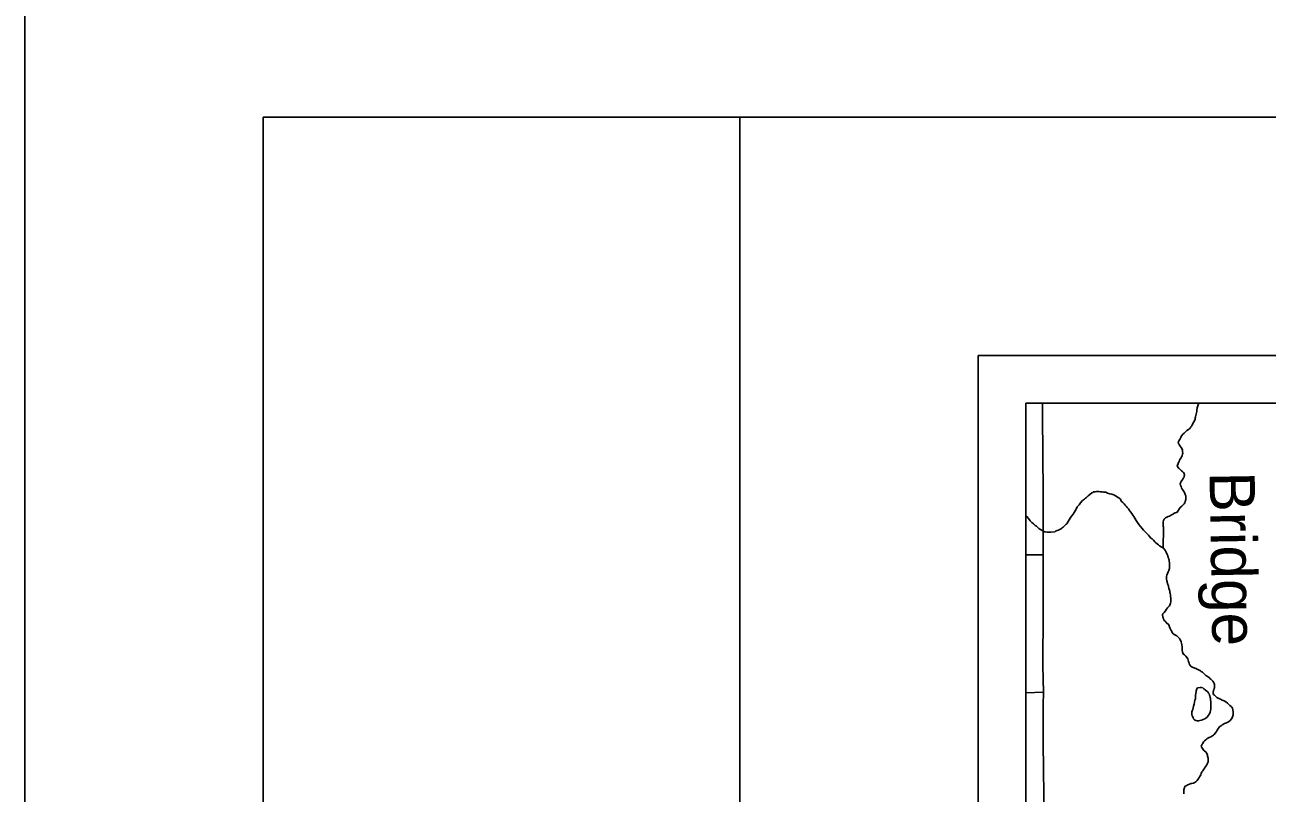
# Model space of a CAD drawing. Extents: x -10.1 to 68, y -9.5 to 29.2.
# Drawn here: x 0 to 2.607, y 20.082 to 21.694 of the extents above; entities that cross this region are included whole.
import ezdxf

# ---------------------------------------------------------------- set-up
doc = ezdxf.new("R2010")
doc.units = 0
for name, color, linetype in [('GM_X_County_Road', 7, 'Continuous'), ('GM_X_Minor_Lake', 7, 'Continuous'), ('GM_X_Minor_River', 7, 'Continuous'), ('GM_X_Minor_River_Text', 7, 'Continuous'), ('GM_X_Township_Subdivision', 7, 'Continuous'), ('SH_Border', 7, 'Continuous'), ('SH_Cut_Line', 7, 'Continuous'), ('SH_Data', 7, 'Continuous')]:
    doc.layers.add(name, color=color, linetype=linetype)

msp = doc.modelspace()

# ---------------------------------------------------------------- linework, layer by layer
at = {"layer": 'GM_X_County_Road'}
msp.add_lwpolyline([(2.1422, 19.6238), (2.1411, 19.7415), (2.1397, 19.8811), (2.1388, 19.955), (2.1384, 20.0244), (2.1379, 20.0776), (2.1367, 20.1872), (2.1367, 20.2668), (2.1372, 20.2932), (2.1361, 20.3491), (2.1363, 20.463), (2.1363, 20.582), (2.1367, 20.6308), (2.1363, 20.7113), (2.135, 20.874), (2.1349, 20.9)], dxfattribs=at)
at = {"layer": 'GM_X_Minor_Lake'}
for points in [[(2.4606, 20.3027), (2.4663, 20.3035), (2.4686, 20.3032), (2.4713, 20.3025), (2.4736, 20.3002), (2.4771, 20.2976), (2.4801, 20.2958), (2.4821, 20.2939), (2.4832, 20.2917), (2.4848, 20.2898), (2.4856, 20.2875), (2.4864, 20.2856), (2.4872, 20.2822), (2.488, 20.2799), (2.488, 20.2773), (2.4885, 20.2742), (2.4885, 20.2712), (2.4887, 20.2632), (2.4887, 20.2602), (2.4884, 20.2575), (2.4877, 20.2548), (2.4869, 20.2518), (2.4855, 20.2483), (2.4836, 20.2456), (2.4822, 20.2433), (2.4807, 20.2414), (2.4777, 20.2391), (2.4758, 20.2375), (2.4724, 20.236), (2.469, 20.2348), (2.4652, 20.2339), (2.4626, 20.2331), (2.4603, 20.2331), (2.4572, 20.2338), (2.4542, 20.2357), (2.4522, 20.2379), (2.4511, 20.2402), (2.4491, 20.2436), (2.4483, 20.2466), (2.4483, 20.2485), (2.4486, 20.2523), (2.4493, 20.2546), (2.4504, 20.2573), (2.4515, 20.2603), (2.4522, 20.2638), (2.4533, 20.268), (2.4543, 20.2722), (2.455, 20.2767), (2.4561, 20.2794), (2.4561, 20.2813), (2.456, 20.2836), (2.4564, 20.287), (2.4567, 20.2905), (2.4574, 20.2939), (2.4577, 20.2966), (2.4581, 20.2985), (2.4592, 20.3004), (2.4606, 20.3027)], [(2.4606, 20.3027), (2.4592, 20.3004), (2.4581, 20.2985), (2.4577, 20.2966), (2.4574, 20.2939), (2.4567, 20.2905), (2.4564, 20.287), (2.456, 20.2836), (2.4561, 20.2813), (2.4561, 20.2794), (2.455, 20.2767), (2.4543, 20.2722), (2.4533, 20.268), (2.4522, 20.2638), (2.4515, 20.2603), (2.4504, 20.2573), (2.4493, 20.2546), (2.4486, 20.2523), (2.4483, 20.2485), (2.4483, 20.2466), (2.4491, 20.2436), (2.4511, 20.2402), (2.4522, 20.2379), (2.4542, 20.2357), (2.4572, 20.2338), (2.4603, 20.2331), (2.4626, 20.2331), (2.4652, 20.2339), (2.469, 20.2348), (2.4724, 20.236)], [(2.4724, 20.236), (2.4758, 20.2375), (2.4777, 20.2391), (2.4807, 20.2414), (2.4822, 20.2433), (2.4836, 20.2456), (2.4855, 20.2483), (2.4869, 20.2518), (2.4877, 20.2548), (2.4884, 20.2575), (2.4887, 20.2602), (2.4887, 20.2632), (2.4885, 20.2712), (2.4885, 20.2742), (2.488, 20.2773), (2.488, 20.2799), (2.4872, 20.2822), (2.4864, 20.2856), (2.4856, 20.2875), (2.4848, 20.2898), (2.4832, 20.2917), (2.4821, 20.2939), (2.4801, 20.2958), (2.4771, 20.2976), (2.4736, 20.3002), (2.4713, 20.3025), (2.4686, 20.3032), (2.4663, 20.3035), (2.4606, 20.3027)]]:
    msp.add_lwpolyline(points, dxfattribs=at)
at = {"layer": 'GM_X_Minor_River'}
for points in [[(2.3882, 20.5963), (2.389, 20.6377), (2.3889, 20.6396), (2.3885, 20.6415), (2.3885, 20.6434), (2.3884, 20.646), (2.3884, 20.6483), (2.3887, 20.6506), (2.3891, 20.6536), (2.3905, 20.6563), (2.3935, 20.6594), (2.3962, 20.661), (2.3992, 20.6622), (2.4014, 20.663), (2.4056, 20.6653), (2.4078, 20.6665), (2.4105, 20.6681), (2.4139, 20.6696), (2.4161, 20.6708), (2.418, 20.6712), (2.4243, 20.6808), (2.4273, 20.6836), (2.4288, 20.6855), (2.4322, 20.689), (2.4336, 20.6909), (2.4347, 20.6939), (2.4351, 20.6959), (2.4358, 20.6978), (2.4358, 20.7004), (2.4361, 20.7027), (2.4357, 20.7054), (2.4349, 20.7084), (2.4341, 20.7103), (2.4333, 20.7122), (2.4321, 20.7144), (2.4313, 20.7163), (2.4286, 20.7197), (2.427, 20.7223), (2.4259, 20.725), (2.425, 20.728), (2.4242, 20.7307), (2.4246, 20.7326), (2.4264, 20.7356), (2.4275, 20.7376), (2.4298, 20.7406), (2.4313, 20.7429), (2.4324, 20.7449), (2.4327, 20.7471), (2.4331, 20.7491), (2.4326, 20.7521), (2.4311, 20.7547), (2.4291, 20.7566), (2.4272, 20.7581), (2.4218, 20.7629), (2.4199, 20.7644), (2.4175, 20.769), (2.419, 20.7713), (2.4201, 20.7732), (2.4208, 20.7755), (2.4219, 20.7778), (2.423, 20.7801), (2.4241, 20.7824), (2.4256, 20.7847), (2.4267, 20.7866), (2.4286, 20.7901), (2.4293, 20.7927), (2.4296, 20.795), (2.4292, 20.7977), (2.4288, 20.8011), (2.428, 20.8037), (2.4264, 20.8067), (2.4244, 20.8098), (2.4229, 20.812), (2.4213, 20.8143), (2.4202, 20.8162), (2.4209, 20.8192), (2.4227, 20.8227), (2.4238, 20.825), (2.4253, 20.828), (2.426, 20.8299), (2.4275, 20.8322), (2.4297, 20.8349), (2.4327, 20.8373), (2.4353, 20.8396), (2.4383, 20.8423), (2.4417, 20.845), (2.4447, 20.8474), (2.4466, 20.85), (2.4484, 20.852), (2.4495, 20.8543), (2.4528, 20.8608), (2.4539, 20.8627), (2.4554, 20.8665), (2.4557, 20.8688), (2.4565, 20.8711), (2.4568, 20.8738), (2.4575, 20.8768), (2.4582, 20.8795), (2.4589, 20.8822), (2.4593, 20.8852), (2.4596, 20.8902)], [(2.4596, 20.8902), (2.461, 20.8944), (2.4625, 20.8982), (2.4632, 20.9)], [(2.1, 20.6644), (2.1022, 20.6619), (2.1057, 20.6577), (2.1095, 20.6532), (2.113, 20.6495), (2.1161, 20.6469), (2.118, 20.645), (2.12, 20.6435), (2.1223, 20.6421), (2.1257, 20.6391), (2.1277, 20.6372), (2.1296, 20.6357), (2.1323, 20.6338), (2.1346, 20.6324), (2.1365, 20.6313), (2.1392, 20.6302), (2.1418, 20.6298), (2.1453, 20.6291), (2.1475, 20.6292), (2.1502, 20.6292), (2.1529, 20.6289), (2.1608, 20.6301), (2.1627, 20.6313), (2.1661, 20.6325), (2.1687, 20.6337), (2.171, 20.6345), (2.1729, 20.6353), (2.1748, 20.6368), (2.1766, 20.6384), (2.1785, 20.6396), (2.1811, 20.6423), (2.1849, 20.6461), (2.1867, 20.6477), (2.1878, 20.6496), (2.1893, 20.6519), (2.1912, 20.655), (2.1934, 20.6588), (2.1964, 20.6627), (2.1993, 20.6673), (2.2019, 20.6707), (2.2038, 20.6738), (2.2056, 20.6773), (2.2082, 20.6822), (2.2119, 20.6869), (2.2152, 20.6911), (2.219, 20.6954), (2.2231, 20.6988), (2.2257, 20.7008), (2.2276, 20.7023), (2.2295, 20.7043), (2.2313, 20.7058), (2.2343, 20.7082), (2.2388, 20.7116), (2.2411, 20.7124), (2.243, 20.7136), (2.2456, 20.714), (2.2487, 20.7149), (2.2509, 20.7149), (2.2532, 20.7145), (2.2566, 20.7142), (2.2601, 20.7139), (2.2635, 20.7132), (2.2658, 20.7132), (2.2684, 20.7129), (2.2719, 20.7114), (2.2768, 20.71), (2.2807, 20.7093), (2.2829, 20.7086), (2.2852, 20.7075), (2.2872, 20.7064), (2.2898, 20.7045), (2.2929, 20.703), (2.2956, 20.7012), (2.2987, 20.6982), (2.3006, 20.6944), (2.3041, 20.6918), (2.3064, 20.6888), (2.3088, 20.6862), (2.3111, 20.6839), (2.313, 20.6813), (2.3154, 20.6779), (2.3181, 20.6745), (2.32, 20.6719), (2.3224, 20.6685), (2.3247, 20.6651), (2.3266, 20.6618), (2.3294, 20.6569), (2.3317, 20.6535), (2.3344, 20.6493), (2.3372, 20.6456)], [(2.3372, 20.6456), (2.3407, 20.6411), (2.3442, 20.6369), (2.3473, 20.6332), (2.3503, 20.6298), (2.3538, 20.6261), (2.3573, 20.6231), (2.36, 20.6201), (2.3623, 20.6167), (2.3654, 20.6149), (2.3681, 20.6122), (2.3708, 20.6092), (2.3731, 20.607), (2.3785, 20.6025), (2.3808, 20.6003), (2.3843, 20.5984), (2.387, 20.5973), (2.3901, 20.5947), (2.392, 20.5925), (2.3932, 20.5898), (2.3944, 20.5876), (2.3955, 20.5853), (2.3975, 20.5815), (2.3983, 20.5789), (2.3991, 20.5766), (2.3999, 20.5743), (2.4007, 20.5713), (2.4011, 20.5687), (2.4016, 20.5652), (2.402, 20.5622), (2.402, 20.5599), (2.4017, 20.5573), (2.4017, 20.5546), (2.4014, 20.5527), (2.4003, 20.5489), (2.3992, 20.5462), (2.3963, 20.5389), (2.3956, 20.5359), (2.3953, 20.5332), (2.3957, 20.5305), (2.3961, 20.5271), (2.3969, 20.5252), (2.3977, 20.5218), (2.3985, 20.5192), (2.3993, 20.5169), (2.3998, 20.5146), (2.4006, 20.5116), (2.4018, 20.5078), (2.4022, 20.5056), (2.4026, 20.5029), (2.403, 20.5002), (2.4035, 20.4976), (2.4039, 20.4942), (2.4043, 20.4904), (2.4044, 20.4866), (2.4045, 20.4832), (2.4037, 20.4805), (2.403, 20.4782), (2.4016, 20.4747), (2.3993, 20.4728), (2.3978, 20.4705), (2.3956, 20.4678), (2.393, 20.464), (2.3904, 20.4605), (2.3874, 20.4582), (2.3871, 20.4555), (2.3879, 20.4509), (2.3891, 20.4479), (2.3895, 20.4449), (2.3926, 20.4423), (2.3949, 20.44), (2.4003, 20.4348), (2.4011, 20.4329), (2.4019, 20.4306), (2.4027, 20.4288), (2.4039, 20.4254), (2.4051, 20.4227), (2.4063, 20.4208), (2.4074, 20.4189), (2.4094, 20.4159), (2.4132, 20.4137), (2.4155, 20.4122), (2.4174, 20.4115), (2.4209, 20.4081), (2.4228, 20.4063), (2.4244, 20.4036), (2.4256, 20.4014), (2.4264, 20.3991), (2.4272, 20.3965), (2.4276, 20.393), (2.4281, 20.3889), (2.4285, 20.3854), (2.4285, 20.3832), (2.4286, 20.3809), (2.429, 20.3782), (2.4294, 20.3763), (2.4306, 20.3737), (2.4333, 20.3718), (2.436, 20.3692), (2.4387, 20.3658), (2.4399, 20.3632)], [(2.4399, 20.3632), (2.4411, 20.3609), (2.4415, 20.3579), (2.4423, 20.356), (2.4431, 20.3541), (2.4439, 20.3515), (2.4458, 20.3485), (2.4489, 20.3459), (2.4512, 20.3451), (2.4566, 20.3433), (2.4585, 20.3426), (2.4611, 20.3411), (2.4642, 20.34), (2.4665, 20.3385), (2.4684, 20.337), (2.4707, 20.3356), (2.4727, 20.3337), (2.475, 20.3314), (2.4781, 20.3288), (2.4804, 20.3274), (2.4823, 20.3255), (2.4846, 20.324), (2.4865, 20.3225), (2.4885, 20.3206), (2.4904, 20.3188), (2.4923, 20.3165), (2.4939, 20.3146), (2.4954, 20.3116), (2.4959, 20.3094), (2.4963, 20.3071), (2.4963, 20.3048), (2.4963, 20.3029), (2.4956, 20.301), (2.4949, 20.2987), (2.4942, 20.2968), (2.4935, 20.2937), (2.4935, 20.2907), (2.4943, 20.2888), (2.4959, 20.2869), (2.4989, 20.2843), (2.5012, 20.2824), (2.5055, 20.2802), (2.5089, 20.2788), (2.5124, 20.2769), (2.5162, 20.2751), (2.5196, 20.2729), (2.5231, 20.2706), (2.5254, 20.2684), (2.5285, 20.2658), (2.5308, 20.2635), (2.5324, 20.2617), (2.5339, 20.2598), (2.5356, 20.2522), (2.5356, 20.2499), (2.5353, 20.2476), (2.5353, 20.2457), (2.5349, 20.2438), (2.5335, 20.24), (2.5316, 20.2373), (2.529, 20.2342), (2.5253, 20.2315), (2.5215, 20.2295), (2.5174, 20.2276), (2.5147, 20.2264), (2.5125, 20.2248), (2.5098, 20.2229), (2.5076, 20.2213), (2.5046, 20.2182), (2.5031, 20.2159), (2.5016, 20.2136), (2.5005, 20.2113), (2.4983, 20.2082), (2.4957, 20.2048), (2.4938, 20.2032), (2.4916, 20.2017), (2.4882, 20.1997), (2.4848, 20.1981), (2.4818, 20.1969), (2.4799, 20.1954), (2.4777, 20.1938), (2.475, 20.1915), (2.4728, 20.1896), (2.4713, 20.1861), (2.4702, 20.1842), (2.4684, 20.18), (2.4696, 20.1773), (2.4708, 20.1755), (2.4735, 20.1713), (2.4754, 20.1698), (2.4785, 20.1676), (2.4801, 20.1646), (2.4812, 20.1616), (2.4817, 20.1593), (2.4821, 20.157), (2.4829, 20.1551), (2.4829, 20.1517), (2.483, 20.1498), (2.4826, 20.1475), (2.4815, 20.1445), (2.4801, 20.141), (2.4782, 20.1383)], [(2.4782, 20.1383), (2.4767, 20.1364), (2.4756, 20.1345), (2.4738, 20.1318), (2.4719, 20.1283), (2.4697, 20.1264), (2.4682, 20.1226), (2.4671, 20.1203), (2.466, 20.118), (2.4649, 20.1157), (2.4634, 20.1134), (2.4612, 20.1103), (2.4597, 20.1084), (2.4567, 20.1053), (2.4518, 20.1029), (2.4488, 20.1021), (2.4469, 20.1017), (2.4435, 20.1005), (2.4416, 20.0997), (2.439, 20.0985), (2.4367, 20.097), (2.4345, 20.0962), (2.4334, 20.0935), (2.4319, 20.0885), (2.4316, 20.0855), (2.4321, 20.0805)]]:
    msp.add_lwpolyline(points, dxfattribs=at)
at = {"layer": 'GM_X_Township_Subdivision'}
for points in [[(2.1, 20.5817), (2.1134, 20.5815), (2.1363, 20.582)], [(2.1372, 20.2932), (2.1, 20.2923)]]:
    msp.add_lwpolyline(points, dxfattribs=at)
at = {"layer": 'SH_Border'}
for points in [[(0.5, 21.5), (1.5, 21.5), (1.5, 0.5), (0.5, 0.5)], [(1.5, 21.5), (33.5, 21.5), (33.5, 0.5), (1.5, 0.5)]]:
    msp.add_lwpolyline(points, close=True, dxfattribs=at)
at = {"layer": 'SH_Cut_Line'}
msp.add_lwpolyline([(0, 0), (34, 0), (34, 22), (0, 22)], close=True, dxfattribs=at)
at = {"layer": 'SH_Data'}
for p, q in [((2, 21), (9, 21)), ((2, 21), (2, 14)), ((2.1, 20.9), (2.1, 14.1)), ((2.1, 20.9), (8.9, 20.9))]:
    msp.add_line(p, q, dxfattribs=at)

# ---------------------------------------------------------------- texts
at = {"layer": 'GM_X_Minor_River_Text'}
msp.add_text('Bridge', height=0.09476, rotation=270.97, dxfattribs=at).set_placement((2.4856, 20.7557))

doc.saveas('drawing.dxf')
